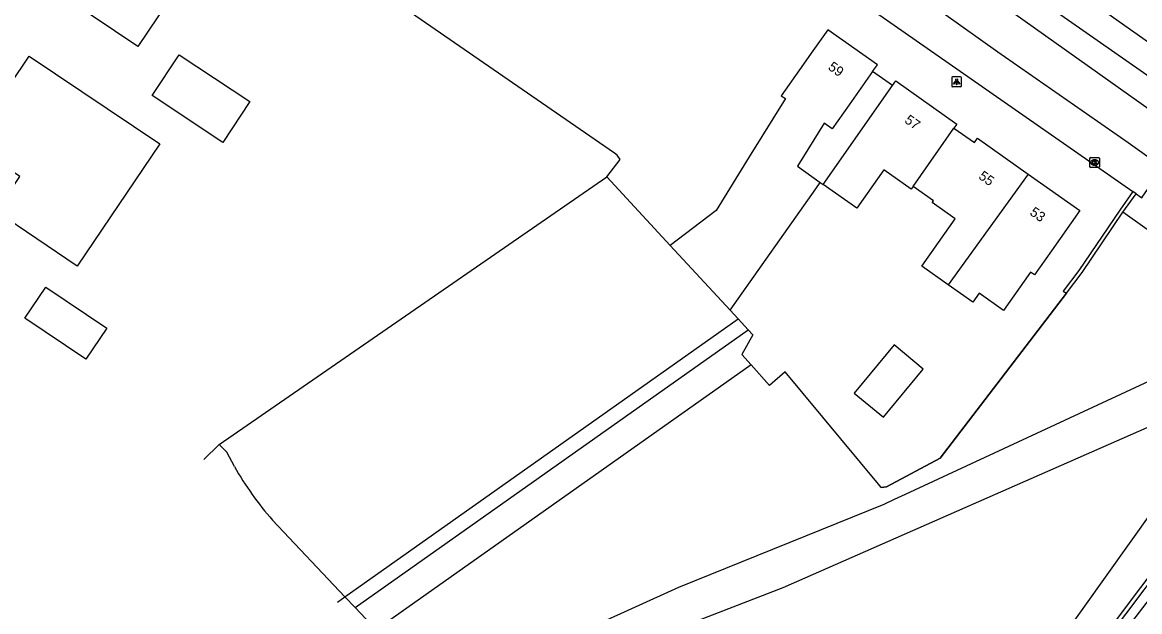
# Model space of a CAD drawing. Extents: x 163863 to 164644, y 379566 to 382155.
# Drawn here: x 164174.8 to 164288.5, y 381747.5 to 381807.4 of the extents above; entities that cross this region are included whole.
import ezdxf

# ---------------------------------------------------------------- set-up
doc = ezdxf.new("R2010")
doc.units = 0
for name, color, linetype in [('IMGEO_Erf', 7, 'Continuous'), ('IMGEO_Groenvoorziening', 7, 'Continuous'), ('IMGEO_Haag', 7, 'Continuous'), ('IMGEO_Hek', 7, 'Continuous'), ('IMGEO_Kolk', 7, 'Continuous'), ('IMGEO_Lichtpunt', 7, 'Continuous'), ('IMGEO_Loofbos', 7, 'Continuous'), ('IMGEO_Muur', 7, 'Continuous'), ('IMGEO_Pand', 7, 'Continuous'), ('IMGEO_Pand_nummerreeks', 7, 'Continuous'), ('IMGEO_Parkeervlak_open', 7, 'Continuous'), ('IMGEO_Rijbaan_lokaal_gesloten', 7, 'Continuous'), ('IMGEO_Voetpad_onverhard', 7, 'Continuous'), ('IMGEO_Waterloop', 7, 'Continuous')]:
    doc.layers.add(name, color=color, linetype=linetype)

msp = doc.modelspace()

# ---------------------------------------------------------------- linework, layer by layer
at = {"layer": 'IMGEO_Erf'}
msp.add_lwpolyline([(164234.24, 381791.72), (164235.6, 381793.48), (164235.29, 381793.93), (164235.04, 381794.14), (164205.96, 381814.21), (164212.36, 381823.54)], dxfattribs=at)
at = {"layer": 'IMGEO_Groenvoorziening'}
msp.add_lwpolyline([(164248.65, 381776.18), (164249.11, 381775.69), (164247.99, 381773.68), (164248.93, 381772.63)], dxfattribs=at)
at = {"layer": 'IMGEO_Haag'}
for points in [[(164287.78, 381790.23), (164286.44, 381788.36), (164282.29, 381782.23), (164280.68, 381780.12), (164281.01, 381779.9)], [(164286.77, 381788.13), (164288.11, 381790)], [(164281.01, 381779.9), (164282.62, 381782), (164286.77, 381788.13)]]:
    msp.add_lwpolyline(points, dxfattribs=at)
at = {"layer": 'IMGEO_Hek'}
msp.add_lwpolyline([(164262.18, 381760.15), (164262.71, 381760.21), (164268.18, 381763.14), (164281.01, 381779.9)], dxfattribs=at)
at = {"layer": 'IMGEO_Kolk'}
for p, q in [((164283.39, 381792.76), (164283.39, 381793.62)), ((164283.46, 381793.69), (164284.31, 381793.69)), ((164283.88, 381793.47), (164283.9, 381793.47)), ((164284.39, 381793.62), (164284.39, 381792.76)), ((164284.31, 381792.69), (164283.46, 381792.69)), ((164283.9, 381792.91), (164283.87, 381792.91))]:
    msp.add_line(p, q, dxfattribs=at)
for points in [[(164283.39, 381792.76), (164283.39, 381793.62)], [(164283.46, 381793.69), (164284.31, 381793.69)], [(164283.71, 381793.39), (164283.83, 381793.39), (164283.83, 381793.24), (164283.96, 381793.39), (164284.13, 381793.39), (164283.98, 381793.24), (164284.13, 381792.99), (164283.98, 381792.99), (164283.9, 381793.15), (164283.83, 381793.09), (164283.83, 381792.99), (164283.71, 381792.99), (164283.71, 381793.39)], [(164284.39, 381793.62), (164284.39, 381792.76)], [(164284.31, 381792.69), (164283.46, 381792.69)]]:
    msp.add_lwpolyline(points, dxfattribs=at)
for centre, start, end in [((164283.46, 381793.61), 91.552, 178.448), ((164283.46, 381793.61), 91.552, 178.448), ((164284.31, 381793.61), 1.552, 88.448), ((164284.31, 381793.61), 1.552, 88.448), ((164283.46, 381792.77), 181.552, 268.448), ((164283.46, 381792.77), 181.552, 268.448), ((164284.31, 381792.77), 271.552, 358.448), ((164284.31, 381792.77), 271.552, 358.448)]:
    msp.add_arc(centre, 0.0765, start, end, dxfattribs=at)
for centre, major_axis, ratio, start_param, end_param in [((164283.87, 381793.19), (-0.387, 0.002), 0.722429, 4.712389, 7.853982), ((164283.9, 381793.19), (-0.39, 0.002), 0.717154, 1.570796, 4.712389)]:
    msp.add_ellipse(centre, major_axis=major_axis, ratio=ratio, start_param=start_param, end_param=end_param, dxfattribs=at)
at = {"layer": 'IMGEO_Lichtpunt'}
for p, q in [((164269.35, 381801.8), (164269.35, 381800.99)), ((164269.35, 381801.8), (164269.35, 381800.99)), ((164270.25, 381801.89), (164269.44, 381801.89)), ((164270.25, 381801.89), (164269.44, 381801.89)), ((164270.34, 381800.99), (164270.34, 381801.8)), ((164270.34, 381800.99), (164270.34, 381801.8)), ((164269.44, 381800.9), (164270.25, 381800.9)), ((164269.44, 381800.9), (164270.25, 381800.9))]:
    msp.add_line(p, q, dxfattribs=at)
for points in [[(164269.72, 381801.46), (164269.76, 381801.44), (164269.57, 381801.17), (164269.53, 381801.2), (164269.72, 381801.46)], [(164269.82, 381801.42), (164269.87, 381801.42), (164269.87, 381801.09), (164269.82, 381801.09), (164269.82, 381801.42)], [(164269.93, 381801.44), (164269.97, 381801.46), (164270.16, 381801.2), (164270.12, 381801.17), (164269.93, 381801.44)]]:
    msp.add_lwpolyline(points, dxfattribs=at)
msp.add_circle((164269.85, 381801.6), 0.0994, dxfattribs=at)
for centre, start, end in [((164269.44, 381801.8), 90, 180), ((164269.44, 381801.8), 90, 180), ((164270.25, 381801.8), 0, 90), ((164270.25, 381801.8), 0, 90), ((164269.44, 381800.99), 180, 270), ((164269.44, 381800.99), 180, 270), ((164270.25, 381800.99), 270, 0), ((164270.25, 381800.99), 270, 360)]:
    msp.add_arc(centre, 0.0946, start, end, dxfattribs=at)
at = {"layer": 'IMGEO_Loofbos'}
for points in [[(164194.82, 381764.54), (164234.24, 381791.72)], [(164240.69, 381784.76), (164234.24, 381791.72)], [(164303.49, 381776.26), (164286.77, 381788.13)], [(164281.01, 381779.9), (164268.18, 381763.14), (164262.71, 381760.21), (164262.18, 381760.15), (164261.9, 381760.49), (164252.41, 381771.92), (164250.79, 381770.54), (164248.93, 381772.63)], [(164247.62, 381777.29), (164246.8, 381778.18)], [(164248.93, 381772.63), (164210.77, 381745.7)]]:
    msp.add_lwpolyline(points, dxfattribs=at)
at = {"layer": 'IMGEO_Muur'}
msp.add_lwpolyline([(164235.04, 381794.14), (164205.96, 381814.21), (164212.36, 381823.54)], dxfattribs=at)
at = {"layer": 'IMGEO_Pand'}
for points in [[(164179.4, 381809.78), (164187.8, 381822.24), (164192.88, 381818.82), (164194.17, 381820.71), (164206.57, 381812.36), (164205.7, 381811.06), (164201.78, 381813.7), (164200.08, 381811.17), (164193.61, 381815.53), (164186.52, 381804.99), (164179.4, 381809.78)], [(164261.3, 381802.45), (164261.78, 381803.13), (164256.73, 381806.69), (164255.21, 381804.53), (164253.85, 381802.61), (164252, 381799.98), (164252.44, 381799.7), (164248.75, 381793.76), (164245.37, 381788.31), (164240.69, 381784.76)], [(164172.13, 381788.21), (164174.53, 381791.77), (164169.52, 381795.15), (164175.48, 381804), (164188.77, 381795.08), (164180.35, 381782.64), (164172.13, 381788.21)], [(164187.99, 381799.99), (164190.75, 381804.14), (164197.92, 381799.38), (164195.17, 381795.23), (164187.99, 381799.99)], [(164261.3, 381802.45), (164258.9, 381799.05), (164257.19, 381796.63), (164256.35, 381797.18), (164253.64, 381792.82), (164255.96, 381791.17)], [(164263.33, 381801.02), (164261.3, 381802.45)], [(164263.33, 381801.02), (164263.67, 381801.49), (164269.85, 381797.09), (164269.57, 381796.69)], [(164256.25, 381790.97), (164263.33, 381801.02)], [(164265.42, 381790.74), (164269.57, 381796.69)], [(164269.57, 381796.69), (164271.67, 381795.23), (164271.96, 381795.65), (164277.13, 381792.01)], [(164265.42, 381790.74), (164265.23, 381790.47), (164262.45, 381792.44), (164259.7, 381788.54), (164256.25, 381790.97)], [(164246.8, 381778.18), (164255.51, 381790.52), (164255.96, 381791.17)], [(164255.96, 381791.17), (164256.25, 381790.97)], [(164277.13, 381792.01), (164269, 381780.74)], [(164277.13, 381792.01), (164282.38, 381788.3), (164279.5, 381784.22), (164277.77, 381781.77), (164277.37, 381782.05), (164274.63, 381778.16), (164272.14, 381779.91), (164271.49, 381778.98), (164269, 381780.74)], [(164269, 381780.74), (164266.29, 381782.65), (164269.69, 381787.47), (164267.35, 381789.12), (164267.48, 381789.3), (164265.42, 381790.74)], [(164246.8, 381778.18), (164240.69, 381784.76)], [(164177.16, 381780.53), (164183.37, 381776.34), (164181.25, 381773.19), (164175.03, 381777.38), (164177.16, 381780.53)], [(164259.43, 381769.76), (164262.39, 381767.32), (164266.43, 381772.2), (164263.48, 381774.65), (164259.43, 381769.76)]]:
    msp.add_lwpolyline(points, dxfattribs=at)
at = {"layer": 'IMGEO_Parkeervlak_open'}
for points in [[(164256.01, 381812.39), (164287.78, 381790.23)], [(164288.11, 381790), (164287.78, 381790.23)], [(164288.11, 381790), (164288.68, 381789.6), (164288.79, 381789.76), (164289.68, 381791.02)]]:
    msp.add_lwpolyline(points, dxfattribs=at)
at = {"layer": 'IMGEO_Rijbaan_lokaal_gesloten'}
for points in [[(164242.76, 381832.06), (164272.36, 381810.74), (164289.67, 381798.44), (164312.34, 381782.45)], [(164290.86, 381792.66), (164287.31, 381795.18), (164274.05, 381804.4), (164268.51, 381808.32), (164257.97, 381815.61)]]:
    msp.add_lwpolyline(points, dxfattribs=at)
at = {"layer": 'IMGEO_Voetpad_onverhard'}
for points in [[(164303.49, 381776.26), (164291.35, 381771.86), (164264.62, 381759.45), (164263.5, 381758.93), (164262.44, 381758.43), (164241.55, 381750), (164220.61, 381740.51), (164216.3, 381738.03), (164214.93, 381737.24), (164212.4, 381737.16), (164209.89, 381736.86), (164207.42, 381736.34), (164205.01, 381735.6), (164202.67, 381734.64), (164200.43, 381733.48), (164199.53, 381732.94), (164085.49, 381652.45), (164019.17, 381605.94), (164016.82, 381609.1)], [(164248.01, 381711.61), (164278.67, 381737.67), (164282.91, 381742.46), (164288.58, 381750), (164297.87, 381762.34), (164306.86, 381773.91)], [(164244.52, 381712.92), (164222.03, 381737.72), (164227.2, 381740.33), (164252.2, 381750), (164290.62, 381766.86), (164293.86, 381765.63), (164294.55, 381764.48), (164280.26, 381744.42), (164244.52, 381712.92)]]:
    msp.add_lwpolyline(points, dxfattribs=at)
at = {"layer": 'IMGEO_Waterloop'}
for points in [[(164362.02, 381753.2), (164361.43, 381751.86), (164361.27, 381751.98), (164350.84, 381759.48), (164291.42, 381800.51), (164261.83, 381821.18), (164221.97, 381849.02), (164223.06, 381850.62)], [(164223.06, 381850.62), (164244.45, 381836.35), (164263.51, 381823.64), (164264.6, 381822.91), (164293.41, 381802.56), (164333.2, 381774)], [(164207.61, 381749.03), (164247.62, 381777.29)], [(164248.65, 381776.18), (164247.62, 381777.29)], [(164208.63, 381747.96), (164248.65, 381776.18)], [(164280.13, 381736.69), (164280.15, 381736.16), (164297.15, 381715.02), (164296.61, 381714.6), (164296.14, 381715.2), (164283.99, 381730.76), (164279.31, 381736.01), (164279.02, 381736.19), (164248.92, 381711.15), (164248.75, 381711.35), (164248.58, 381711.56), (164278.96, 381737.38), (164283.23, 381742.2), (164288.91, 381749.75), (164298.2, 381762.09), (164306.94, 381773.35), (164307.82, 381772.74), (164306.69, 381771.27), (164290.54, 381750.25), (164280.45, 381737.13), (164280.13, 381736.69)], [(164193.25, 381763.01), (164194.82, 381764.54)], [(164196.36, 381762.28), (164195.58, 381763.75), (164194.82, 381764.54)], [(164207.61, 381749.03), (164200.24, 381756.84)], [(164206.85, 381748.5), (164207.61, 381749.03)], [(164208.63, 381747.96), (164207.61, 381749.03)], [(164210.77, 381745.7), (164208.63, 381747.96)]]:
    msp.add_lwpolyline(points, dxfattribs=at)
msp.add_arc((164223.47, 381777.49), 31.08, 209.2898, 221.626, dxfattribs=at)

# ---------------------------------------------------------------- texts
at = {"layer": 'IMGEO_Pand_nummerreeks'}
for s, p in [('59', (164256.69, 381802.71)), ('57', (164264.47, 381797.31)), ('55', (164272, 381791.61)), ('53', (164277.21, 381787.94))]:
    msp.add_text(s, height=1, rotation=324.7917, dxfattribs=at).set_placement(p)

doc.saveas('drawing.dxf')
